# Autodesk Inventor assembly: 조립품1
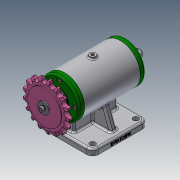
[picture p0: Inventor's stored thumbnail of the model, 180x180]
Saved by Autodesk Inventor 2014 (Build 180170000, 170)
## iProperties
Created: 2019-06
Part Number: 조립품1
Document SubType Name: Assembly
Designer: net
Author: net
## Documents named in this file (11)
- C:\Users\net\Desktop\490604V1039\조립품1.iam
- C:\Users\net\Desktop\490604V1039\베어링 6203.ipt
- C:\Users\net\Desktop\490604V1039\본체.ipt
- C:\Users\net\Desktop\490604V1039\볼트 M4.ipt
- C:\Users\net\Desktop\490604V1039\스프로킷.ipt
- C:\Users\net\Desktop\490604V1039\스프링와셔.ipt
- C:\Users\net\Desktop\490604V1039\오일 실 17 30 5.ipt
- C:\Users\net\Desktop\490604V1039\축.ipt
- C:\Users\net\Desktop\490604V1039\커버.ipt
- C:\Users\net\Desktop\490604V1039\키 4x4x12.ipt
- C:\Users\net\Desktop\490604V1039\평와셔.ipt
